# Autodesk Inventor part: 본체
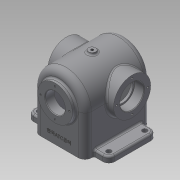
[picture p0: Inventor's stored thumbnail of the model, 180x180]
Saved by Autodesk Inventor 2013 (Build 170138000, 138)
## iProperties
Created: 2019-05
Part Number: 본체
Material: 알루미늄 6061
Document SubType Name: Modeling
Designer: mduedu
Density: 2.71 g/cm^3
Mass: 1068.38 g
Surface Area: 1001.38 cm^2
Volume: 394.235 cm^3
Author: mduedu
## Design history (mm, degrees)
sketch "스케치1"
  geometry: L1 (-55, 0)-(55, 0); L2 (55, 0)-(55, 110); L3 (55, 110)-(-55, 110); L4 (-55, 110)-(-55, 0); 2 further points
  constraints: 8 end point, 2 parallel, 1 coincident, 1 horizontal, 1 midpoint, 1 perpendicular
  dimensions: "d0" = 110 distance of L3.end L1.start; "d2" = 110 distance of L2.end L3.end
extrude "돌출1" new body sketch "스케치1" stored distance "d3" = 86; taper "d4" = 0 deg
fillet "모깎기1"
fillet "모깎기2" dims "d5" = 11
feature "쉘1" dims "d6" = 8
sketch "스케치2"
  geometry: C1 r 29 at (-32, 67); A1 r 43 centre (-32, 67) between (11, 67) and (-75, 67) reference; 1 further point
  constraints: 1 centre point, 1 coincident
  dimensions: "d7" = 58 diameter of C1
extrude "돌출2" join sketch "스케치2" distance "d8" = 7; taper "d9" = 0 deg
fillet "모깎기3" dims "d10" = 3
hole "구멍1" diameter "d13" = 33; stored, may be unused: countersink angle "d17" = 90 deg, drill point angle "d19" = 118 deg; dims "d11" = 10, "d12" = 10, "d14" = 6, "d15" = 4, "d16" = 2, "d18" = 8
node "작업 평면1"
sketch "스케치3"
  geometry: L1 (18, -29)-(18, 29) reference; L2 (-99, 0)-(-99, 32) reference; C1 r 31 at (-56, 0); 2 further points
  constraints: 1 centre point, 1 horizontal alignment, 1 midpoint
  dimensions: "d21" = 62 diameter of C1; "d24" = 43 distance from line of C1.centre L2
extrude "돌출3" join sketch "스케치3" stored distance "d25" = 5; taper "d26" = 0 deg
hole "구멍2" diameter "d29" = 40; stored, may be unused: countersink angle "d33" = 90 deg, drill point angle "d35" = 0 deg; dims "d27" = 10, "d28" = 10, "d30" = 6, "d31" = 4, "d32" = 2, "d34" = 16
hole "구멍3" diameter "d38" = 35; stored, may be unused: countersink angle "d42" = 90 deg, drill point angle "d44" = 0 deg; dims "d36" = 10, "d37" = 10, "d39" = 6, "d40" = 4, "d41" = 2, "d43" = 16
fillet "모깎기4" dims "d45" = 3
chamfer "모따기1" distance "d46" = 1; stored, may be unused: second distance "d47" = 2, angle "d48" = 45 deg
chamfer "모따기2" distance "d49" = 1; stored, may be unused: second distance "d50" = 2, angle "d51" = 45 deg
fillet "모깎기5" dims "d52" = 0.3
node "작업 평면2"
sketch "스케치4"
  geometry: L1 (11, 75)-(11, 11) reference; C1 r 6 at (-44, 43); 1 further point
  constraints: 1 centre point, 1 coincident
  dimensions: "d54" = 12 diameter of C1; "d67" = 55 distance from line of point (-44, 43) L1 (derived)
extrude "돌출4" join sketch "스케치4" stored distance "d55" = 5; taper "d56" = 0 deg
hole "구멍4" diameter "d59" = 4.134; stored, may be unused: countersink angle "d63" = 90 deg, drill point angle "d65" = 0 deg; dims "d57" = 10, "d58" = 10, "d60" = 6, "d61" = 4, "d62" = 2, "d64" = 16
fillet "모깎기6" dims "d66" = 3
sketch "스케치5"
  geometry: L1 (47, -32)-(47, 32) reference; L2 (44, 35)-(-44, 35) reference; L3 (-47, 32)-(-47, -32) reference; L4 (-44, -35)-(44, -35) reference; L5 (-44, -43)-(44, -43) reference; L6 (-55, -32)-(-55, 32) reference; L7 (44, 43)-(-44, 43) reference; L8 (55, 32)-(55, -32) reference; L9 (40, 43)-(-40, 43); L10 (-40, 43)-(-40, 68); L11 (-40, 68)-(40, 68); L12 (40, 68)-(40, 43); A1 r 3 centre (44, -32) between (44, -35) and (47, -32) reference; A2 r 3 centre (44, 32) between (47, 32) and (44, 35) reference; A3 r 3 centre (-44, 32) between (-44, 35) and (-47, 32) reference; A4 r 3 centre (-44, -32) between (-47, -32) and (-44, -35) reference; A5 r 11 centre (44, -32) between (44, -43) and (55, -32) reference; A6 r 11 centre (-44, -32) between (-55, -32) and (-44, -43) reference; A7 r 11 centre (-44, 32) between (-44, 43) and (-55, 32) reference; A8 r 11 centre (44, 32) between (55, 32) and (44, 43) reference; 1 further point
  constraints: 8 end point, 2 parallel, 1 horizontal, 1 perpendicular, 1 point on line
  dimensions: "d68" = 15 distance between parallel lines of L12 L8; "d71" = 80 distance of L10.end L11.end; "d72" = 25 distance between parallel lines of L11 L7
extrude "돌출5" join sketch "스케치5" distance "d73" = 10; taper "d74" = 0 deg
fillet "모깎기7" dims "d76" = 10
sketch "스케치6"
  geometry: L1 (-40, -43)-(-40, -58) reference; L2 (-30, -68)-(30, -68) reference; L3 (40, -58)-(40, -43) reference; L4 (-40, -43)-(40, -43) reference; C1 r 4 at (-30, -58); C2 r 4 at (30, -58); A1 r 10 centre (30, -58) between (30, -68) and (40, -58) reference; A2 r 10 centre (-30, -58) between (-40, -58) and (-30, -68) reference; 1 further point
  constraints: 2 centre point, 2 coincident, 1 equal radius
  dimensions: "d77" = 8 diameter of C1
extrude "돌출6" cut sketch "스케치6" stored distance "d78" = 10; taper "d79" = 0 deg
fillet "모깎기8" dims "d80" = 3
fillet "모깎기9" dims "d81" = 3
fillet "모깎기10" dims "d82" = 3
fillet "모깎기11" dims "d83" = 3
sketch "스케치7"
  geometry: L1 (64, 0)-(0, 0) reference; 4 further points
  constraints: 2 midpoint, 2 vertical alignment, 1 other
  dimensions: "d85" = 15 distance of point (32, 15) point (32, 0)
feature "엠보싱1" sketch "스케치7" dims "d7" = 58, "d86" = 0.5, "d87" = 0
sketch "스케치8"
  geometry: 4 further points
  constraints: 4 other
hole "구멍5" sketch "스케치8" at (0, 24), (-24, 0), (0, -24), (24, 0) diameter "d88" = 3.242; stored, may be unused: countersink angle "d92" = 90 deg, drill point angle "d94" = 120 deg; dims "d89" = 8, "d90" = 4, "d91" = 2, "d93" = 10
sketch "스케치9"
  geometry: 4 further points
  constraints: 4 other
hole "구멍7" sketch "스케치9" at (-26, 0), (0, -26), (26, 0), (0, 26) diameter "d95" = 3.242; stored, may be unused: countersink angle "d99" = 90 deg, drill point angle "d101" = 120 deg; dims "d96" = 8, "d97" = 4, "d98" = 2, "d100" = 10
sketch "스케치10"
  geometry: 4 further points
  constraints: 4 other
hole "구멍9" sketch "스케치10" at (0, -26), (26, 0), (-26, 0), (0, 26) diameter "d102" = 3.242; stored, may be unused: countersink angle "d106" = 90 deg, drill point angle "d108" = 120 deg; dims "d103" = 8, "d104" = 4, "d105" = 2, "d107" = 10
node "솔리드1"
mirror "대칭1"
mirror "대칭2"
node "투영된 루프1"
node "투영된 루프2"
other parameters: "d53" = -113
